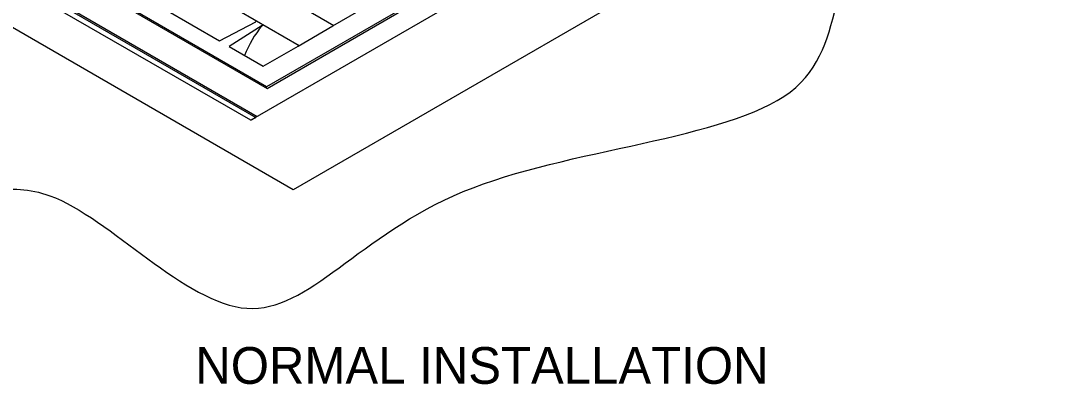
# Model space of a CAD drawing. Extents: x 99862 to 103151, y 100000 to 102076.
# Drawn here: x 102133 to 102695, y 100777 to 100974 of the extents above; entities that cross this region are included whole.
import ezdxf

# ---------------------------------------------------------------- set-up
doc = ezdxf.new("R2010")
doc.units = 0
for name, color, linetype in [('Level 1', 7, 'Continuous'), ('Level 2', 7, 'Continuous'), ('Level 4', 7, 'Continuous'), ('Level 5', 7, 'Continuous'), ('Level 7', 7, 'Continuous')]:
    doc.layers.add(name, color=color, linetype=linetype)

msp = doc.modelspace()

# ---------------------------------------------------------------- linework, layer by layer
at = {"layer": 'Level 1'}
for p, q in [((102266.93, 100938.46), (102118.43, 101024.19)), ((102415.42, 101024.19), (102266.93, 100938.46)), ((102211.24, 100980.82), (102241.29, 100963.47)), ((102303.64, 100971.63), (102285.08, 100982.35)), ((102303.04, 100971.56), (102321.98, 100982.49)), ((102284.7, 100960.7), (102252, 100979.58)), ((102241.29, 100963.47), (102261.12, 100973.89)), ((102264.65, 100971.85), (102246.6, 100960.4)), ((102284.1, 100960.62), (102303.04, 100971.56)), ((102246.6, 100960.4), (102265.16, 100949.69)), ((102265.16, 100949.69), (102284.1, 100960.62)), ((102266.93, 100937.78), (102266.93, 100938.46))]:
    msp.add_line(p, q, dxfattribs=at)
for centre, major_axis, ratio, start_param, end_param in [((102274.89, 100951.31), (15.39, 31.5), 0.568458, 1.174816, 1.711668), ((102261.09, 100972.89), (-0.7, -1.04), 0.58246, 3.968328, 4.397124), ((102264.68, 100970.81), (0.55, 1.12), 0.568458, 0.74602, 1.174816), ((102302.97, 100970.58), (-0.69, -1.04), 0.531476, 3.95991, 4.388707), ((102284.03, 100959.64), (-0.69, -1.04), 0.531476, 3.95991, 4.388707)]:
    msp.add_ellipse(centre, major_axis=major_axis, ratio=ratio, start_param=start_param, end_param=end_param, dxfattribs=at)
at = {"layer": 'Level 2'}
for p, q in [((102267.22, 100937.61), (102565.97, 101110.09)), ((102090.44, 101021.3), (102261.92, 100922.3)), ((102116.96, 101024.36), (102267.22, 100937.61))]:
    msp.add_line(p, q, dxfattribs=at)
at = {"layer": 'Level 4'}
for p, q in [((102597.79, 101116.22), (102258.38, 100920.26)), ((102258.38, 100920.26), (102085.14, 101020.28)), ((102087.79, 101021.81), (102261.03, 100921.79)), ((102258.38, 100920.26), (102261.03, 100921.79))]:
    msp.add_line(p, q, dxfattribs=at)
at = {"layer": 'Level 5'}
msp.add_open_spline([(101846, 100972.03), (101845.01, 100942.03), (101905.62, 100922.42), (101999.33, 100949.11), (102064.13, 100845.94), (102141.72, 100913.98), (102262.88, 100773.42), (102344.11, 100900.16), (102604.53, 100914.51), (102549.58, 101055.6), (102853.06, 101117.14), (102680.94, 101171.22), (102661.14, 101280.99), (102558.16, 101285.8), (102543.13, 101333.37), (102536.01, 101339.65)], degree=3, dxfattribs=at)
at = {"layer": 'Level 7'}
for p, q in [((102663.2, 101102.95), (102281.36, 100882.5)), ((102281.36, 100882.5), (102042.71, 101020.28))]:
    msp.add_line(p, q, dxfattribs=at)

# ---------------------------------------------------------------- texts
at = {"layer": 'Level 1'}
msp.add_text('NORMAL INSTALLATION', height=20, dxfattribs=at).set_placement((102228.16, 100776.9))

doc.saveas('drawing.dxf')
